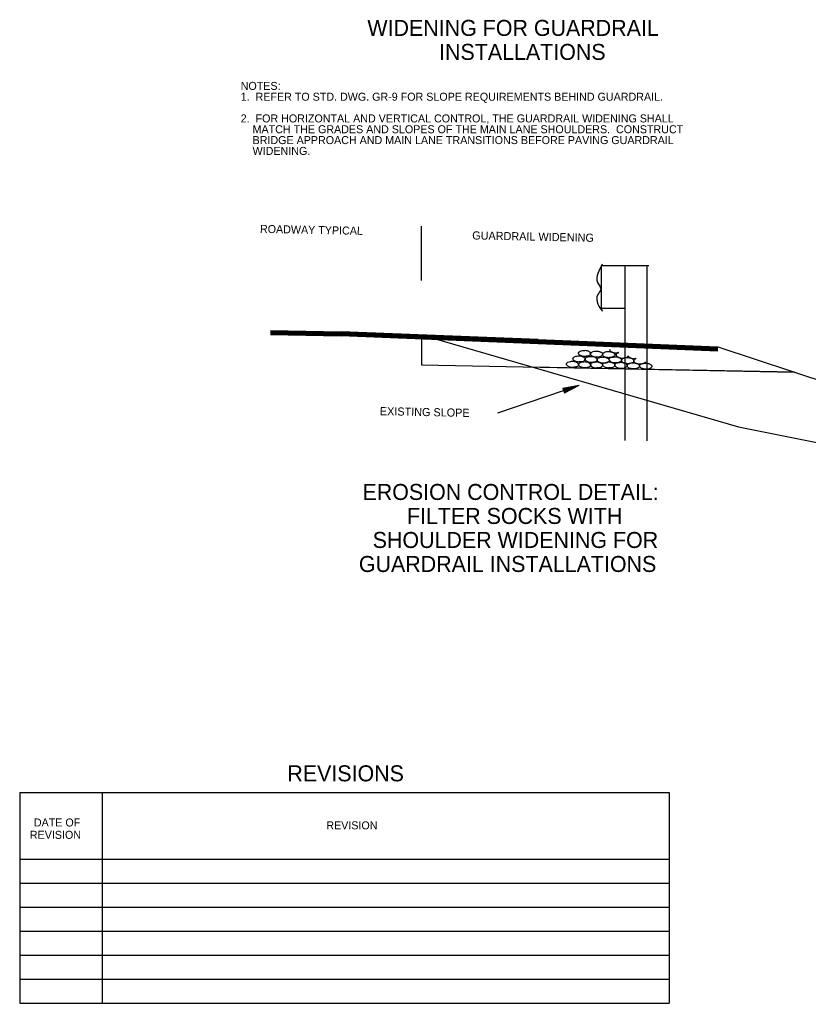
# Model space of a CAD drawing. Extents: x 1929624 to 1932072, y 596315 to 605954.
# Drawn here: x 1930529 to 1931120, y 604566 to 605304 of the extents above; entities that cross this region are included whole.
import ezdxf

# ---------------------------------------------------------------- set-up
doc = ezdxf.new("R2010")
doc.units = 0
for name, color, linetype in [('B_Concrete hidden', 7, 'Continuous'), ('B_Dimensions', 7, 'Continuous'), ('Default', 7, 'Continuous')]:
    doc.layers.add(name, color=color, linetype=linetype)

msp = doc.modelspace()

# ---------------------------------------------------------------- linework, layer by layer
at = {"layer": 'B_Concrete hidden'}
for p, q in [((1930830.2065945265, 605108.175365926), (1930830.2065945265, 605148.9526236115)), ((1931109.840413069, 605039.4162674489), (1930913.1498343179, 605043.328263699))]:
    msp.add_line(p, q, dxfattribs=at)
for points in [[(1930830.2065945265, 605067.3981082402), (1931067.7495339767, 604998.4639595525), (1931172.6438580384, 604977.5975679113), (1931225.4898072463, 604975.9952981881), (1931273.100889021, 604980.3740293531), (1931377.3049588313, 604980.384810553)], [(1930830.2065945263, 605064.345639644), (1930830.2065945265, 605044.9779291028), (1931109.840413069, 605039.4162674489)]]:
    msp.add_lwpolyline(points, dxfattribs=at)
at = {"layer": 'B_Dimensions'}
for p, q in [((1930529.0756926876, 604724.2192428), (1931015.760569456, 604724.2192427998)), ((1930529.0756926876, 604724.2192428), (1930529.0756926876, 604566.2601906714)), ((1930590.8698693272, 604724.2187429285), (1930590.8693051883, 604566.2601906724)), ((1931015.760569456, 604724.2192427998), (1931015.7605694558, 604566.2601906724)), ((1930529.075192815, 604674.2320428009), (1931015.7605694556, 604674.2320428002)), ((1930529.0751928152, 604656.2366508), (1931015.7605694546, 604656.2366508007)), ((1930529.0751928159, 604638.2407589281), (1931015.760569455, 604638.2419040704)), ((1930529.0751928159, 604620.2458667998), (1931015.7605694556, 604620.2458668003)), ((1930529.0751928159, 604602.2509746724), (1931015.760569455, 604602.2509746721)), ((1930529.0761925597, 604584.2540830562), (1931015.7605694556, 604584.2546556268)), ((1930529.0756926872, 604566.2601906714), (1931015.7605694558, 604566.2601906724))]:
    msp.add_line(p, q, dxfattribs=at)
at = {"layer": 'Default'}
for p, q in [((1930964.8505143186, 605119.4276624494), (1930964.8505143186, 605087.5904099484)), ((1930964.8505143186, 605119.4276624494), (1931000.5013480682, 605119.4276624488)), ((1930982.6882330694, 605119.4276624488), (1930982.6882330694, 604988.2404674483)), ((1930999.0743305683, 605119.2800399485), (1930999.0743305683, 604988.117448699)), ((1930964.8505143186, 605087.5904099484), (1930982.6882330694, 605087.5904099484)), ((1930716.9431293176, 605070.8598599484), (1930770.1118330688, 605069.8018986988)), ((1930716.9431293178, 605070.1217474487), (1930770.1118330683, 605069.0637861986)), ((1930716.9677330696, 605069.3836349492), (1930770.1118330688, 605068.3256736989)), ((1930716.9923368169, 605068.6455224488), (1930770.1118330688, 605067.5875611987)), ((1930717.016940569, 605067.9074099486), (1930770.0626255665, 605066.8494486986)), ((1930717.016940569, 605067.8089949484), (1930770.1118330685, 605066.7510336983)), ((1930917.6359180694, 605060.9445486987), (1930770.0134180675, 605066.8494486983)), ((1930917.6851255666, 605062.4207736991), (1930770.0626255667, 605068.3256736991)), ((1930917.6851255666, 605061.6826611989), (1930770.062625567, 605067.5875611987)), ((1930917.7343330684, 605063.8969986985), (1930770.1118330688, 605069.8018986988)), ((1930917.7343330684, 605063.158886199), (1930770.1118330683, 605069.0637861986)), ((1930917.6359180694, 605060.8461336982), (1930770.1118330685, 605066.7510336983)), ((1930917.6933268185, 605063.158886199), (1931052.3496505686, 605057.7706649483)), ((1930917.7343330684, 605063.8969986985), (1931052.390656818, 605058.5087774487)), ((1930917.6113143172, 605060.9445486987), (1931052.2676380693, 605055.5563274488)), ((1930917.6359180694, 605061.6826611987), (1931052.2922418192, 605056.2944399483)), ((1930917.668723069, 605062.4207736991), (1931052.3250468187, 605057.0325524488)), ((1931052.390656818, 605058.5087774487), (1931287.4005935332, 604980.3848105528)), ((1930887.4080051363, 605009.1368631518), (1930948.3231806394, 605029.8180830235)), ((1930936.0851229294, 605027.4809040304), (1930948.3231806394, 605029.8180830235)), ((1930936.0851229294, 605027.4809040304), (1930937.2890685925, 605024.0263307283)), ((1930936.1653176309, 605027.2199568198), (1930946.3922864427, 605029.1581768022)), ((1930936.3055233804, 605026.899610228), (1930944.3198554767, 605028.4186875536)), ((1930936.4005589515, 605026.6004365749), (1930942.4047555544, 605027.7543560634)), ((1930936.517073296, 605026.2867278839), (1930940.475120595, 605027.068545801)), ((1930936.5603007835, 605025.9850357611), (1930938.5116844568, 605026.3836889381)), ((1930936.7870333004, 605025.4871385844), (1930938.5116844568, 605026.3836889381)), ((1930936.8798562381, 605025.1800677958), (1930940.475120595, 605027.068545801)), ((1930937.0039618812, 605024.9238516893), (1930942.4047555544, 605027.7543560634)), ((1930937.053827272, 605024.6458509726), (1930944.3198554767, 605028.4186875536)), ((1930937.1637037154, 605024.3084508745), (1930946.3922864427, 605029.1581768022)), ((1930937.2890685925, 605024.0263307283), (1930948.3231806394, 605029.8180830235))]:
    msp.add_line(p, q, dxfattribs=at)
for points in [[(1930965.7116455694, 605120.4610199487), (1930962.3655355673, 605113.5473661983), (1930962.1933093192, 605106.8059386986), (1930964.6044768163, 605101.6145474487), (1930962.3655355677, 605097.677947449), (1930962.3655355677, 605090.4198411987), (1930965.9084755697, 605085.1792424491)], [(1930952.5978468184, 605055.8843774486), (1930950.9739993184, 605055.785962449), (1930949.005699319, 605055.1954724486), (1930947.9723418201, 605054.260529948), (1930947.8247193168, 605053.719247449), (1930948.3167943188, 605052.7350974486), (1930948.907284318, 605052.2922299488), (1930950.0390568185, 605051.7509474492), (1930951.6136968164, 605051.3080799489), (1930952.4502243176, 605051.3080799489), (1930953.6312043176, 605051.4064949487), (1930954.9598068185, 605051.5541174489), (1930955.9931643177, 605051.9477774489), (1930956.8788993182, 605052.7843049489), (1930957.0265218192, 605053.4240024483), (1930956.7312768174, 605054.3097374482), (1930956.0915793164, 605054.9002274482), (1930955.402674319, 605055.2938874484), (1930954.32010932, 605055.7367549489), (1930953.6312043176, 605055.8843774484), (1930952.5978468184, 605055.8843774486)], [(1930971.2121542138, 605056.5838072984), (1930971.2085764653, 605056.550472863), (1930971.207654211, 605056.4829663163), (1930971.2152680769, 605056.4171545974), (1930971.2884169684, 605056.1489738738), (1930971.4052744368, 605055.8852320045), (1930971.5624493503, 605055.6291120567), (1930971.6550961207, 605055.5049050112), (1930971.7565505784, 605055.383797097), (1930972.012914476, 605055.1346910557), (1930972.2978330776, 605054.9409295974), (1930972.56193522, 605054.7970138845), (1930972.828234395, 605054.6655261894), (1930973.0999741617, 605054.5487214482), (1930973.3803980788, 605054.4488545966), (1930974.16155054, 605054.2276018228), (1930974.9550380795, 605054.0551945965), (1930975.372944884, 605053.9870892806), (1930975.5821297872, 605053.9654687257), (1930975.791565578, 605053.9567795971), (1930976.3819994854, 605053.9850919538), (1930976.6773754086, 605054.016870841), (1930976.9725455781, 605054.0551945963), (1930977.4940953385, 605054.1363252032), (1930978.011138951, 605054.2364844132)], [(1930948.5218255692, 605051.775551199), (1930946.7995630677, 605051.5787211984), (1930944.8804705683, 605051.0866461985), (1930943.8963205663, 605050.1517036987), (1930943.7486980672, 605049.6104211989), (1930944.24077307, 605048.5770636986), (1930944.8312630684, 605048.1341961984), (1930945.9138280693, 605047.5437061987), (1930947.4884680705, 605047.1500461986), (1930948.2757880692, 605047.1500461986), (1930949.505975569, 605047.2484611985), (1930950.8837855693, 605047.3468761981), (1930951.9171430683, 605047.8389511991), (1930952.802878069, 605048.6754786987), (1930952.9505005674, 605049.3151761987), (1930952.655255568, 605050.2009111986), (1930951.9171430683, 605050.7914011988), (1930951.2282380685, 605051.0866461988), (1930950.145673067, 605051.5295136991), (1930949.505975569, 605051.7263436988), (1930948.5218255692, 605051.775551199)], [(1930957.452986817, 605051.357287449), (1930955.8291393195, 605051.3080799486), (1930953.8608393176, 605050.6683824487), (1930952.8766893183, 605049.7334399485), (1930952.7290668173, 605049.1921574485), (1930953.270349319, 605048.1587999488), (1930953.8116318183, 605047.7159324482), (1930954.894196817, 605047.223857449), (1930956.468836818, 605046.8301974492), (1930957.3053643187, 605046.7317824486), (1930958.4863443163, 605046.8301974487), (1930959.814946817, 605047.0762349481), (1930960.848304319, 605047.4698949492), (1930961.8324543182, 605048.2572149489), (1930961.9800768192, 605048.8969124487), (1930961.6848318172, 605049.7826474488), (1930960.9467193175, 605050.3731374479), (1930960.2578143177, 605050.8160049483), (1930959.1752493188, 605051.1604574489), (1930958.4863443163, 605051.3080799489), (1930957.452986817, 605051.357287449)], [(1930961.4141905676, 605055.3594974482), (1930959.79034307, 605055.261082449), (1930957.871250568, 605054.5721774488), (1930956.8871005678, 605053.7848574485), (1930956.7394780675, 605053.2435749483), (1930957.2807605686, 605052.2102174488), (1930957.7236280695, 605051.6689349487), (1930958.904608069, 605051.1768599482), (1930960.3808330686, 605050.832407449), (1930961.2173605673, 605050.7339924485), (1930962.4475480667, 605050.7831999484), (1930963.8253580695, 605051.0292374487), (1930964.8095080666, 605051.4721049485), (1930965.8428655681, 605052.2594249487), (1930965.9904880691, 605052.899122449), (1930965.6952430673, 605053.7848574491), (1930964.95713057, 605054.4245549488), (1930964.219018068, 605054.7690074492), (1930963.1364530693, 605055.1134599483), (1930962.4475480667, 605055.261082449), (1930961.4141905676, 605055.3594974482)], [(1930966.548173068, 605050.8570111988), (1930964.9243255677, 605050.7093886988), (1930962.9560255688, 605050.1681061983), (1930961.9226680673, 605049.2331636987), (1930961.775045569, 605048.6918811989), (1930962.3163280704, 605047.7077311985), (1930962.8576105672, 605047.2648636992), (1930963.989383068, 605046.6251661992), (1930965.514815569, 605046.2807136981), (1930966.3513430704, 605046.2807136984), (1930967.5323230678, 605046.3791286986), (1930968.9593405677, 605046.4283361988), (1930969.9434905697, 605046.9204111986), (1930970.8784330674, 605047.7569386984), (1930971.0260555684, 605048.3966361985), (1930970.730810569, 605049.2823711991), (1930970.0419055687, 605049.872861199), (1930969.3037930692, 605050.2173136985), (1930968.2704355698, 605050.5617661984), (1930967.5815305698, 605050.8570111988), (1930966.548173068, 605050.8570111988)], [(1930970.59138932, 605054.9904411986), (1930968.9675418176, 605054.9412336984), (1930966.9992418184, 605054.2523286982), (1930966.0150918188, 605053.366593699), (1930965.867469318, 605052.7761036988), (1930966.4087518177, 605051.7919536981), (1930966.950034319, 605051.3490861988), (1930968.03259932, 605050.8570111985), (1930969.607239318, 605050.4141436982), (1930970.4437668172, 605050.3649361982), (1930971.6247468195, 605050.4633511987), (1930972.9533493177, 605050.7093886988), (1930973.9867068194, 605051.1030486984), (1930974.9708568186, 605051.8903686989), (1930975.1184793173, 605052.4808586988), (1930974.8232343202, 605053.366593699), (1930974.0851218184, 605053.9570836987), (1930973.3962168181, 605054.4491586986), (1930972.3136518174, 605054.7936111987), (1930971.624746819, 605054.9412336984), (1930970.59138932, 605054.9904411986)], [(1930975.503938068, 605051.0866461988), (1930973.8800905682, 605050.8898161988), (1930971.960998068, 605050.3977411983), (1930970.9768480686, 605049.4627986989), (1930970.8292255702, 605048.9215161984), (1930971.370508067, 605047.8881586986), (1930971.9117905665, 605047.4452911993), (1930972.9943555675, 605046.8548011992), (1930974.5689955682, 605046.4611411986), (1930975.3563155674, 605046.4611411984), (1930976.5865030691, 605046.5595561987), (1930977.9151055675, 605046.6579711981), (1930978.9976705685, 605047.1500461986), (1930979.9326130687, 605047.9865736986), (1930980.0802355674, 605048.6262711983), (1930979.784990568, 605049.5120061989), (1930979.046878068, 605050.1024961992), (1930978.3087655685, 605050.3977411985), (1930977.275408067, 605050.8898161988), (1930976.53729557, 605051.0374386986), (1930975.503938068, 605051.0866461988)], [(1930977.868651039, 605054.2856778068), (1930977.5702013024, 605054.1660994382), (1930977.3293792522, 605054.0549398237), (1930977.088921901, 605053.9316465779), (1930976.7968675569, 605053.7485064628), (1930976.5435527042, 605053.5349980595), (1930976.3168849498, 605053.2860782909), (1930976.2097648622, 605053.1467631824), (1930976.1047719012, 605052.9967040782), (1930976.0286230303, 605052.8640477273), (1930975.9757336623, 605052.7265041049), (1930975.950457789, 605052.5887398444), (1930975.949535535, 605052.5212332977), (1930975.9571494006, 605052.4554215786), (1930976.0302982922, 605052.1872408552), (1930976.1471557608, 605051.923498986), (1930976.3043306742, 605051.6673790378), (1930976.3969774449, 605051.5431719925), (1930976.4984319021, 605051.4220640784), (1930976.7547957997, 605051.1729580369), (1930977.0397144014, 605050.9791965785), (1930977.3038165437, 605050.8352808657), (1930977.5701157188, 605050.7037931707), (1930977.8418554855, 605050.5869884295), (1930978.1222794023, 605050.4871215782), (1930978.903431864, 605050.265868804), (1930979.696919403, 605050.0934615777), (1930980.533446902, 605049.9950465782), (1930980.6809425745, 605049.9964993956), (1930980.8285329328, 605050.0020276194), (1930981.1238808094, 605050.0233589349), (1930981.714426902, 605050.0934615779), (1930982.0491794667, 605050.1432486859), (1930982.3814776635, 605050.2007866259), (1930982.7124011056, 605050.2661714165), (1930983.0430294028, 605050.3394990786), (1930983.3089957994, 605050.4135286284), (1930983.5676298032, 605050.5064292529), (1930983.822302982, 605050.6142797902), (1930984.0763869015, 605050.7331590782), (1930984.3547178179, 605050.8793282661), (1930984.6100801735, 605051.048266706), (1930984.8446333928, 605051.2564813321), (1930984.9547813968, 605051.3804756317), (1930985.0605369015, 605051.5204790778), (1930985.130022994, 605051.6404963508), (1930985.1759072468, 605051.762876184)], [(1930984.8041555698, 605050.4469486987), (1930983.1803080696, 605050.3977411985), (1930981.2120080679, 605049.7580436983), (1930980.2278580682, 605048.8231011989), (1930980.0802355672, 605048.2818186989), (1930980.621518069, 605047.2484611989), (1930981.1628005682, 605046.8055936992), (1930982.2453655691, 605046.3135186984), (1930983.82000557, 605045.9198586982), (1930984.656533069, 605045.821443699), (1930985.8375130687, 605045.9198586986), (1930987.1661155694, 605046.1658961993), (1930988.1994730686, 605046.5595561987), (1930989.183623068, 605047.3468761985), (1930989.331245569, 605047.9865736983), (1930989.0360005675, 605048.872308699), (1930988.2978880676, 605049.4627986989), (1930987.60898307, 605049.9056661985), (1930986.526418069, 605050.2501186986), (1930985.8375130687, 605050.3977411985), (1930984.8041555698, 605050.4469486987)], [(1930985.1251233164, 605051.7804091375), (1930985.2087995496, 605051.5768551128), (1930985.3168966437, 605051.3772280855), (1930985.4478756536, 605051.1829725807), (1930985.600197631, 605050.9955331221), (1930985.8565615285, 605050.7464270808), (1930986.1414801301, 605050.5526656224), (1930986.4055822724, 605050.4087499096), (1930986.6718814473, 605050.2772622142), (1930986.943621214, 605050.1604574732), (1930987.2240451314, 605050.060590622), (1930988.0051975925, 605049.839337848), (1930988.7986851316, 605049.6669306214), (1930989.2165919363, 605049.5988253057), (1930989.4257768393, 605049.5772047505), (1930989.6352126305, 605049.5685156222), (1930990.2256465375, 605049.5968279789), (1930990.8161926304, 605049.6669306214), (1930991.1178737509, 605049.7114354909)], [(1930990.7021161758, 605049.8549741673), (1930990.438392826, 605049.7351945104), (1930990.3067715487, 605049.6698375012), (1930990.1751761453, 605049.6008626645), (1930989.8831218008, 605049.4177225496), (1930989.629806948, 605049.2042141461), (1930989.4031391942, 605048.9552943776), (1930989.2960191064, 605048.8159792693), (1930989.1910261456, 605048.6659201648), (1930989.1148772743, 605048.5332638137), (1930989.0619879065, 605048.3957201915), (1930989.0367120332, 605048.257955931), (1930989.0357897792, 605048.190449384), (1930989.0434036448, 605048.1246376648), (1930989.1165525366, 605047.8564569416), (1930989.2334100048, 605047.5927150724), (1930989.3905849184, 605047.3365951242), (1930989.483231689, 605047.2123880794), (1930989.5846861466, 605047.091280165), (1930989.8410500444, 605046.842174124), (1930990.1259686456, 605046.6484126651), (1930990.3900707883, 605046.5044969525), (1930990.656369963, 605046.3730092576), (1930990.9281097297, 605046.2562045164), (1930991.2085336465, 605046.1563376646), (1930991.9896861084, 605045.9350848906), (1930992.7831736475, 605045.7626776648), (1930993.6197011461, 605045.6642626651), (1930993.767196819, 605045.6657154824), (1930993.914787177, 605045.6712437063), (1930994.2101350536, 605045.692575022), (1930994.800681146, 605045.7626776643), (1930995.1354337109, 605045.8124647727), (1930995.4677319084, 605045.8700027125), (1930995.7986553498, 605045.9353875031), (1930996.1292836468, 605046.008715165), (1930996.3952500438, 605046.082744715), (1930996.6538840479, 605046.1756453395), (1930996.9085572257, 605046.2834958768), (1930997.1626411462, 605046.4023751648), (1930997.4409720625, 605046.5485443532), (1930997.6963344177, 605046.7174827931), (1930997.9308876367, 605046.9256974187), (1930998.041035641, 605047.0496917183), (1930998.0944455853, 605047.1175633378), (1930998.146791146, 605047.1896951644), (1930998.1946937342, 605047.2681910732)], [(1930943.5026605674, 605047.6831274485), (1930941.878813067, 605047.6339199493), (1930939.9105130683, 605046.9450149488), (1930938.975570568, 605046.0592799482), (1930938.8279480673, 605045.4687899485), (1930939.3200230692, 605044.4846399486), (1930939.9105130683, 605044.0417724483), (1930940.9438705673, 605043.5496974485), (1930942.56771807, 605043.1068299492), (1930943.3550380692, 605043.0576224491), (1930944.5852255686, 605043.1560374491), (1930945.9138280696, 605043.4020749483), (1930946.9471855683, 605043.7957349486), (1930947.8821280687, 605044.5830549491), (1930948.029750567, 605045.173544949), (1930947.7345055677, 605046.0592799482), (1930946.9963930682, 605046.6497699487), (1930946.307488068, 605047.1418449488), (1930945.224923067, 605047.4862974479), (1930944.5360180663, 605047.6339199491), (1930943.5026605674, 605047.6831274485)], [(1930952.6060480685, 605047.3960836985), (1930950.9822005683, 605047.2484611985), (1930949.0139005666, 605046.6579711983), (1930948.078958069, 605045.7722361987), (1930947.9313355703, 605045.1817461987), (1930948.4234105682, 605044.1975961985), (1930948.9154855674, 605043.754728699), (1930950.047258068, 605043.2626536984), (1930951.572690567, 605042.7705786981), (1930952.4092180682, 605042.7705786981), (1930953.6394055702, 605042.8689936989), (1930955.017215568, 605043.0658236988), (1930956.0013655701, 605043.4102761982), (1930956.9855155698, 605044.2960111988), (1930957.1331380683, 605044.8865011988), (1930956.8378930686, 605045.7722361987), (1930956.099780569, 605046.362726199), (1930955.3616680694, 605046.8055936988), (1930954.328310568, 605047.1992536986), (1930953.63940557, 605047.3468761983), (1930952.6060480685, 605047.3960836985)], [(1930961.4551968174, 605047.264863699), (1930959.8313493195, 605047.0680336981), (1930957.8630493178, 605046.5267511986), (1930956.8788993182, 605045.6410161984), (1930956.7312768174, 605045.0505261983), (1930957.2725593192, 605044.0663761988), (1930957.8138418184, 605043.6235086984), (1930958.896406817, 605043.0330186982), (1930960.4218393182, 605042.6393586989), (1930961.2583668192, 605042.6393586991), (1930962.488554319, 605042.7377736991), (1930963.8171568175, 605042.8361886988), (1930964.8505143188, 605043.2790561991), (1930965.8346643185, 605044.164791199), (1930965.9822868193, 605044.755281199), (1930965.6870418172, 605045.6410161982), (1930964.94892932, 605046.2315061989), (1930964.2108168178, 605046.5759586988), (1930963.1282518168, 605046.9696186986), (1930962.4885543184, 605047.215656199), (1930961.4551968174, 605047.264863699)], [(1930970.7144080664, 605047.2730649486), (1930969.0413530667, 605047.0762349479), (1930967.07305307, 605046.5349524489), (1930966.088903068, 605045.649217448), (1930965.9412805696, 605045.0587274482), (1930966.4825630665, 605044.0745774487), (1930967.0238455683, 605043.6317099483), (1930968.1556180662, 605042.9920124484), (1930969.6810505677, 605042.6475599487), (1930970.4683705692, 605042.6475599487), (1930971.6985580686, 605042.6967674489), (1930973.0763680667, 605042.8443899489), (1930974.1097255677, 605043.2872574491), (1930975.044668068, 605044.1729924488), (1930975.1922905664, 605044.7634824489), (1930974.8970455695, 605045.6492174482), (1930974.1589330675, 605046.239707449), (1930973.4208205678, 605046.5841599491), (1930972.3874630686, 605046.9286124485), (1930971.7477655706, 605047.1254424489), (1930970.7144080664, 605047.2730649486)], [(1930979.784990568, 605046.9040086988), (1930978.0627280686, 605046.7071786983), (1930976.1928430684, 605046.2151036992), (1930975.1594855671, 605045.2801611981), (1930975.0118630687, 605044.7388786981), (1930975.553145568, 605043.7055211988), (1930976.0944280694, 605043.2626536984), (1930977.22620057, 605042.6721636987), (1930978.7516330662, 605042.2785036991), (1930979.5389530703, 605042.2785036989), (1930980.7691405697, 605042.3769186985), (1930982.1961580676, 605042.4753336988), (1930983.1803080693, 605042.9674086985), (1930984.115250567, 605043.8039361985), (1930984.2628730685, 605044.4436336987), (1930983.9676280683, 605045.3293686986), (1930983.2295155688, 605045.9198586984), (1930982.5406105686, 605046.215103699), (1930981.4580455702, 605046.6087636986), (1930980.8183480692, 605046.8548011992), (1930979.784990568, 605046.9040086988)], [(1930989.0606043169, 605046.5267511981), (1930987.4367568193, 605046.4283361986), (1930985.5176643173, 605045.7394311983), (1930984.53351432, 605044.9521111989), (1930984.3858918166, 605044.4108286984), (1930984.9271743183, 605043.3774711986), (1930985.3700418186, 605042.8361886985), (1930986.5510218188, 605042.3441136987), (1930988.027246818, 605041.9996611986), (1930988.8637743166, 605041.9012461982), (1930990.0939618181, 605041.9504536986), (1930991.4717718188, 605042.1964911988), (1930992.4559218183, 605042.6393586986), (1930993.48927932, 605043.4266786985), (1930993.6369018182, 605044.0663761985), (1930993.3416568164, 605044.9521111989), (1930992.6035443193, 605045.5918086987), (1930991.8654318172, 605045.9362611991), (1930990.7828668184, 605046.2807136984), (1930990.0939618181, 605046.4283361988), (1930989.0606043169, 605046.5267511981)], [(1930998.311614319, 605046.3381224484), (1930996.6877668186, 605046.1904999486), (1930994.7194668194, 605045.600009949), (1930993.7845243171, 605044.7142749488), (1930993.6369018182, 605044.1237849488), (1930994.1289768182, 605043.1396349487), (1930994.621051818, 605042.6967674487), (1930995.7528243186, 605042.2046924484), (1930997.2782568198, 605041.7126174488), (1930998.1147843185, 605041.7126174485), (1930999.344971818, 605041.8110324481), (1931000.7227818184, 605042.0078624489), (1931001.7069318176, 605042.3523149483), (1931002.6910818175, 605043.2380499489), (1931002.8387043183, 605043.8285399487), (1931002.543459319, 605044.7142749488), (1931001.805346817, 605045.3047649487), (1931001.0672343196, 605045.7476324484), (1931000.0338768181, 605046.1412924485), (1930999.344971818, 605046.2889149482), (1930998.311614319, 605046.3381224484)]]:
    msp.add_spline(points, degree=3, dxfattribs=at)

# ---------------------------------------------------------------- texts
at = {"layer": 'B_Dimensions'}
for s, height, p in [('REVISIONS', 11.996928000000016, (1930729.680202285, 604732.7165669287)), ('DATE OF', 5.998464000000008, (1930539.7139685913, 604698.8512386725)), ('REVISION', 5.998464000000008, (1930758.8845656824, 604696.7262828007)), ('REVISION', 5.998464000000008, (1930536.7152364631, 604689.6026069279))]:
    msp.add_text(s, height=height, dxfattribs=at).set_placement(p)
at = {"layer": 'Default'}
for s, height, rotation, p in [(' WIDENING FOR GUARDRAIL', 12, 359.9999999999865, (1930785.182631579, 605291.6481762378)), (' INSTALLATIONS ', 12, 359.9999999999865, (1930838.9116354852, 605273.6481762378)), ('ROADWAY TYPICAL', 6, 358.8536972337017, (1930709.126233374, 605143.9912431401)), ('GUARDRAIL WIDENING', 6.075, 358.8536972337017, (1930868.1817790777, 605139.0582229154)), ('EXISTING SLOPE', 6.075, 358.8536972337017, (1930798.9683389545, 605007.2740092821)), ('EROSION CONTROL DETAIL:', 12, 359.9999999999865, (1930785.9837363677, 604943.6945552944)), ('FILTER SOCKS WITH', 12, 359.9999999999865, (1930819.3102333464, 604925.6945552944)), (' SHOULDER WIDENING FOR', 12, 359.9999999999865, (1930789.1699659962, 604907.6945552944)), ('GUARDRAIL INSTALLATIONS', 12, 359.9999999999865, (1930783.2813009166, 604889.6945552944))]:
    msp.add_text(s, height=height, rotation=rotation, dxfattribs=at).set_placement(p)
for s, p in [('NOTES:', (1930694.7070816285, 605251.1718106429)), ('1.  REFER TO STD. DWG. GR-9 FOR SLOPE REQUIREMENTS BEHIND GUARDRAIL.', (1930694.7070816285, 605243.0443614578)), ('2.  FOR HORIZONTAL AND VERTICAL CONTROL, THE GUARDRAIL WIDENING SHALL', (1930694.7070816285, 605226.7894630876)), ('    MATCH THE GRADES AND SLOPES OF THE MAIN LANE SHOULDERS.  CONSTRUCT', (1930694.7070816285, 605218.6620139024)), ('    BRIDGE APPROACH AND MAIN LANE TRANSITIONS BEFORE PAVING GUARDRAIL', (1930694.7070816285, 605210.5345647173)), ('    WIDENING.', (1930694.7070816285, 605202.4071155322))]:
    msp.add_text(s, height=6, dxfattribs=at).set_placement(p)

doc.saveas('drawing.dxf')
